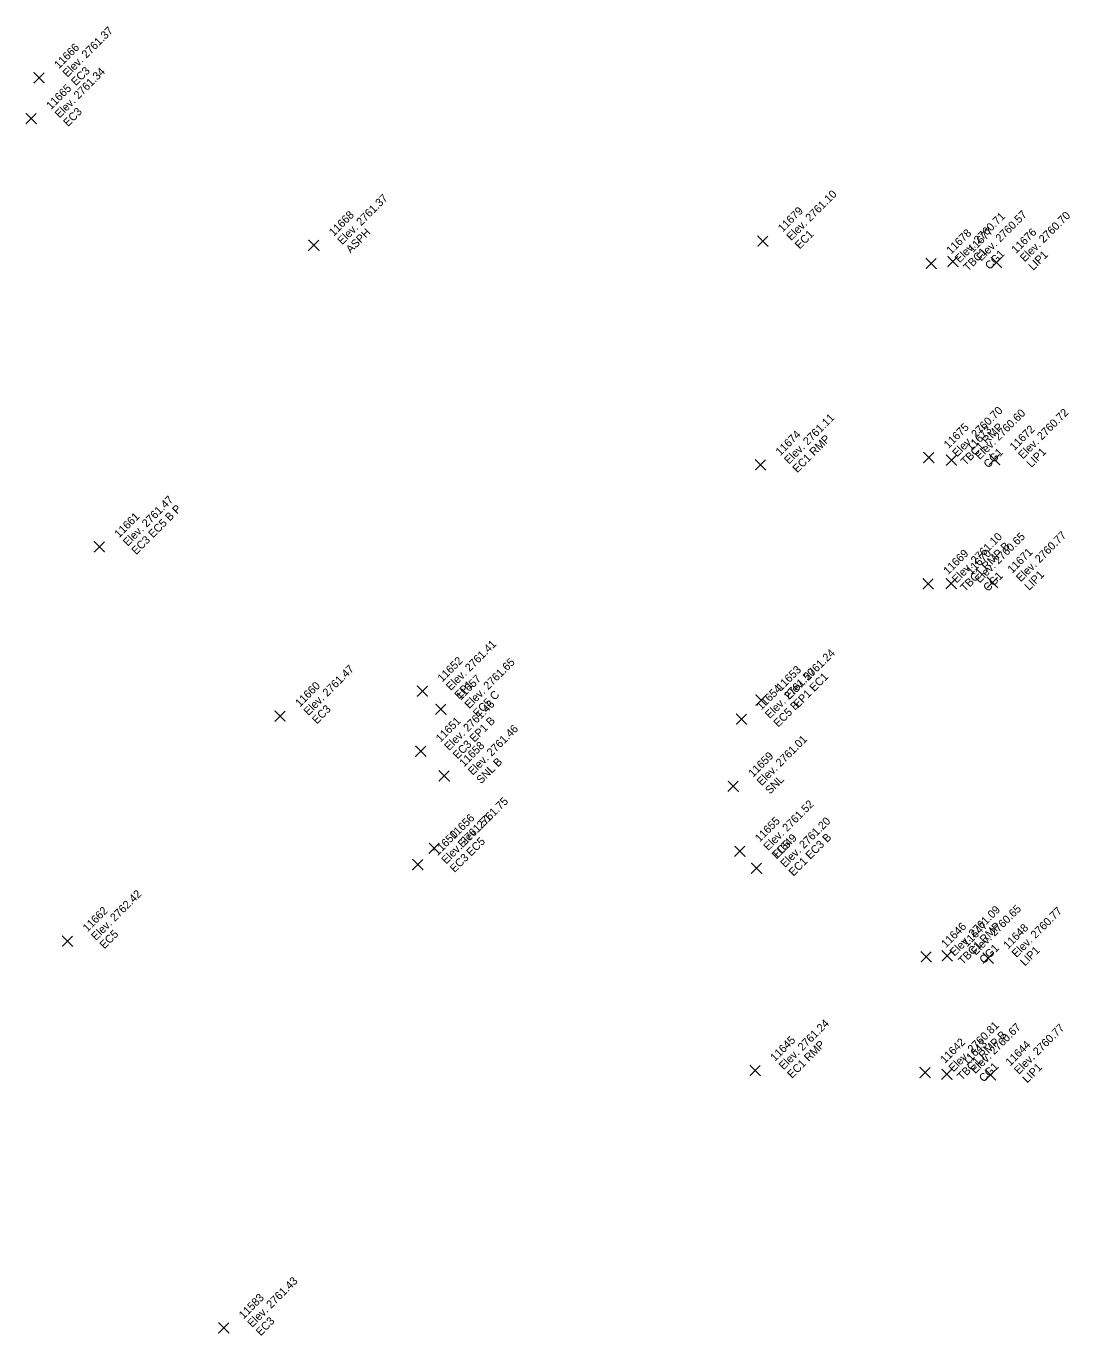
# Model space of a CAD drawing. Extents: x 2493999 to 2503109, y 700767 to 706646.
# Drawn here: x 2502218.73 to 2502250.03, y 701911.21 to 701950.47 of the extents above; entities that cross this region are included whole.
import ezdxf

# ---------------------------------------------------------------- set-up
doc = ezdxf.new("R2010")
doc.units = 0
doc.layers.add('ALG_CL_BLUE_Horiz', color=7, linetype='Continuous')
doc.layers.add('DES_SURFACE_Existing-Ground', color=7, linetype='Continuous')

msp = doc.modelspace()

# ---------------------------------------------------------------- linework, layer by layer
at = {"layer": 'ALG_CL_BLUE_Horiz'}
for points in [[(2502219.122, 701948.922), (2502218.972, 701949.072), (2502219.122, 701948.922), (2502218.972, 701948.772), (2502219.122, 701948.922), (2502219.272, 701948.772), (2502219.122, 701948.922), (2502219.272, 701949.072)], [(2502218.884, 701947.698), (2502218.734, 701947.848), (2502218.884, 701947.698), (2502218.734, 701947.548), (2502218.884, 701947.698), (2502219.034, 701947.548), (2502218.884, 701947.698), (2502219.034, 701947.848)], [(2502240.826, 701944.024), (2502240.676, 701944.174), (2502240.826, 701944.024), (2502240.676, 701943.874), (2502240.826, 701944.024), (2502240.976, 701943.874), (2502240.826, 701944.024), (2502240.976, 701944.174)], [(2502227.36, 701943.902), (2502227.21, 701944.052), (2502227.36, 701943.902), (2502227.21, 701943.752), (2502227.36, 701943.902), (2502227.51, 701943.752), (2502227.36, 701943.902), (2502227.51, 701944.052)], [(2502245.876, 701943.358), (2502245.726, 701943.508), (2502245.876, 701943.358), (2502245.726, 701943.208), (2502245.876, 701943.358), (2502246.026, 701943.208), (2502245.876, 701943.358), (2502246.026, 701943.508)], [(2502246.527, 701943.409), (2502246.377, 701943.559), (2502246.527, 701943.409), (2502246.377, 701943.259), (2502246.527, 701943.409), (2502246.677, 701943.259), (2502246.527, 701943.409), (2502246.677, 701943.559)], [(2502247.828, 701943.383), (2502247.678, 701943.533), (2502247.828, 701943.383), (2502247.678, 701943.233), (2502247.828, 701943.383), (2502247.978, 701943.233), (2502247.828, 701943.383), (2502247.978, 701943.533)], [(2502240.756, 701937.32), (2502240.606, 701937.47), (2502240.756, 701937.32), (2502240.606, 701937.17), (2502240.756, 701937.32), (2502240.906, 701937.17), (2502240.756, 701937.32), (2502240.906, 701937.47)], [(2502245.799, 701937.536), (2502245.649, 701937.686), (2502245.799, 701937.536), (2502245.649, 701937.386), (2502245.799, 701937.536), (2502245.949, 701937.386), (2502245.799, 701937.536), (2502245.949, 701937.686)], [(2502246.482, 701937.458), (2502246.332, 701937.608), (2502246.482, 701937.458), (2502246.332, 701937.308), (2502246.482, 701937.458), (2502246.632, 701937.308), (2502246.482, 701937.458), (2502246.632, 701937.608)], [(2502247.774, 701937.475), (2502247.624, 701937.625), (2502247.774, 701937.475), (2502247.624, 701937.325), (2502247.774, 701937.475), (2502247.924, 701937.325), (2502247.774, 701937.475), (2502247.924, 701937.625)], [(2502220.928, 701934.86), (2502220.778, 701935.01), (2502220.928, 701934.86), (2502220.778, 701934.71), (2502220.928, 701934.86), (2502221.078, 701934.71), (2502220.928, 701934.86), (2502221.078, 701935.01)], [(2502247.709, 701933.794), (2502247.559, 701933.944), (2502247.709, 701933.794), (2502247.559, 701933.644), (2502247.709, 701933.794), (2502247.859, 701933.644), (2502247.709, 701933.794), (2502247.859, 701933.944)], [(2502245.786, 701933.753), (2502245.636, 701933.903), (2502245.786, 701933.753), (2502245.636, 701933.603), (2502245.786, 701933.753), (2502245.936, 701933.603), (2502245.786, 701933.753), (2502245.936, 701933.903)], [(2502246.473, 701933.757), (2502246.323, 701933.907), (2502246.473, 701933.757), (2502246.323, 701933.607), (2502246.473, 701933.757), (2502246.623, 701933.607), (2502246.473, 701933.757), (2502246.623, 701933.907)], [(2502230.618, 701930.534), (2502230.468, 701930.684), (2502230.618, 701930.534), (2502230.468, 701930.384), (2502230.618, 701930.534), (2502230.768, 701930.384), (2502230.618, 701930.534), (2502230.768, 701930.684)], [(2502240.771, 701930.266), (2502240.621, 701930.416), (2502240.771, 701930.266), (2502240.621, 701930.116), (2502240.771, 701930.266), (2502240.921, 701930.116), (2502240.771, 701930.266), (2502240.921, 701930.416)], [(2502231.171, 701929.992), (2502231.021, 701930.142), (2502231.171, 701929.992), (2502231.021, 701929.842), (2502231.171, 701929.992), (2502231.321, 701929.842), (2502231.171, 701929.992), (2502231.321, 701930.142)], [(2502226.346, 701929.787), (2502226.196, 701929.937), (2502226.346, 701929.787), (2502226.196, 701929.637), (2502226.346, 701929.787), (2502226.496, 701929.637), (2502226.346, 701929.787), (2502226.496, 701929.937)], [(2502240.185, 701929.693), (2502240.035, 701929.843), (2502240.185, 701929.693), (2502240.035, 701929.543), (2502240.185, 701929.693), (2502240.335, 701929.543), (2502240.185, 701929.693), (2502240.335, 701929.843)], [(2502230.566, 701928.732), (2502230.416, 701928.882), (2502230.566, 701928.732), (2502230.416, 701928.582), (2502230.566, 701928.732), (2502230.716, 701928.582), (2502230.566, 701928.732), (2502230.716, 701928.882)], [(2502231.272, 701927.994), (2502231.122, 701928.144), (2502231.272, 701927.994), (2502231.122, 701927.844), (2502231.272, 701927.994), (2502231.422, 701927.844), (2502231.272, 701927.994), (2502231.422, 701928.144)], [(2502239.937, 701927.683), (2502239.787, 701927.833), (2502239.937, 701927.683), (2502239.787, 701927.533), (2502239.937, 701927.683), (2502240.087, 701927.533), (2502239.937, 701927.683), (2502240.087, 701927.833)], [(2502230.973, 701925.821), (2502230.823, 701925.971), (2502230.973, 701925.821), (2502230.823, 701925.671), (2502230.973, 701925.821), (2502231.123, 701925.671), (2502230.973, 701925.821), (2502231.123, 701925.971)], [(2502240.135, 701925.735), (2502239.985, 701925.885), (2502240.135, 701925.735), (2502239.985, 701925.585), (2502240.135, 701925.735), (2502240.285, 701925.585), (2502240.135, 701925.735), (2502240.285, 701925.885)], [(2502230.477, 701925.333), (2502230.327, 701925.483), (2502230.477, 701925.333), (2502230.327, 701925.183), (2502230.477, 701925.333), (2502230.627, 701925.183), (2502230.477, 701925.333), (2502230.627, 701925.483)], [(2502240.639, 701925.225), (2502240.489, 701925.375), (2502240.639, 701925.225), (2502240.489, 701925.075), (2502240.639, 701925.225), (2502240.789, 701925.075), (2502240.639, 701925.225), (2502240.789, 701925.375)], [(2502219.976, 701923.042), (2502219.826, 701923.192), (2502219.976, 701923.042), (2502219.826, 701922.892), (2502219.976, 701923.042), (2502220.126, 701922.892), (2502219.976, 701923.042), (2502220.126, 701923.192)], [(2502245.723, 701922.569), (2502245.573, 701922.719), (2502245.723, 701922.569), (2502245.573, 701922.419), (2502245.723, 701922.569), (2502245.873, 701922.419), (2502245.723, 701922.569), (2502245.873, 701922.719)], [(2502246.357, 701922.599), (2502246.207, 701922.749), (2502246.357, 701922.599), (2502246.207, 701922.449), (2502246.357, 701922.599), (2502246.507, 701922.449), (2502246.357, 701922.599), (2502246.507, 701922.749)], [(2502247.583, 701922.529), (2502247.433, 701922.679), (2502247.583, 701922.529), (2502247.433, 701922.379), (2502247.583, 701922.529), (2502247.733, 701922.379), (2502247.583, 701922.529), (2502247.733, 701922.679)], [(2502240.597, 701919.162), (2502240.447, 701919.312), (2502240.597, 701919.162), (2502240.447, 701919.012), (2502240.597, 701919.162), (2502240.747, 701919.012), (2502240.597, 701919.162), (2502240.747, 701919.312)], [(2502245.69, 701919.1), (2502245.54, 701919.25), (2502245.69, 701919.1), (2502245.54, 701918.95), (2502245.69, 701919.1), (2502245.84, 701918.95), (2502245.69, 701919.1), (2502245.84, 701919.25)], [(2502246.346, 701919.049), (2502246.196, 701919.199), (2502246.346, 701919.049), (2502246.196, 701918.899), (2502246.346, 701919.049), (2502246.496, 701918.899), (2502246.346, 701919.049), (2502246.496, 701919.199)], [(2502247.65, 701919.026), (2502247.5, 701919.176), (2502247.65, 701919.026), (2502247.5, 701918.876), (2502247.65, 701919.026), (2502247.8, 701918.876), (2502247.65, 701919.026), (2502247.8, 701919.176)], [(2502224.66, 701911.442), (2502224.51, 701911.592), (2502224.66, 701911.442), (2502224.51, 701911.292), (2502224.66, 701911.442), (2502224.81, 701911.292), (2502224.66, 701911.442), (2502224.81, 701911.592)]]:
    msp.add_lwpolyline(points, dxfattribs=at)

# ---------------------------------------------------------------- texts
at = {"layer": 'DES_SURFACE_Existing-Ground'}
for s, p in [('Elev. 2761.37', (2502219.971, 701948.922)), ('11666', (2502219.716, 701949.177)), ('EC3', (2502220.225, 701948.667)), ('Elev. 2761.34', (2502219.733, 701947.698)), ('11665', (2502219.478, 701947.953)), ('EC3', (2502219.987, 701947.443)), ('Elev. 2761.37', (2502228.209, 701943.902)), ('Elev. 2761.10', (2502241.675, 701944.024)), ('11668', (2502227.954, 701944.157)), ('11679', (2502241.42, 701944.279)), ('Elev. 2760.57', (2502247.376, 701943.409)), ('Elev. 2760.71', (2502246.725, 701943.358)), ('Elev. 2760.70', (2502248.677, 701943.383)), ('ASPH', (2502228.463, 701943.647)), ('EC1', (2502241.929, 701943.769)), ('11678', (2502246.47, 701943.613)), ('11677', (2502247.121, 701943.664)), ('11676', (2502248.422, 701943.638)), ('TBC1', (2502246.979, 701943.103)), ('CG1', (2502247.63, 701943.154)), ('LIP1', (2502248.931, 701943.128)), ('Elev. 2760.70', (2502246.648, 701937.536)), ('Elev. 2761.11', (2502241.605, 701937.32)), ('Elev. 2760.60', (2502247.331, 701937.458)), ('Elev. 2760.72', (2502248.623, 701937.475)), ('11674', (2502241.35, 701937.575)), ('11675', (2502246.393, 701937.791)), ('TBC1 RMP', (2502246.902, 701937.281)), ('11673', (2502247.076, 701937.713)), ('11672', (2502248.368, 701937.73)), ('EC1 RMP', (2502241.859, 701937.065)), ('CG1', (2502247.585, 701937.203)), ('LIP1', (2502248.877, 701937.22)), ('Elev. 2761.47', (2502221.777, 701934.86)), ('EC3 EC5 B P', (2502222.031, 701934.605)), ('11661', (2502221.522, 701935.115)), ('Elev. 2761.10', (2502246.635, 701933.753)), ('Elev. 2760.65', (2502247.322, 701933.757)), ('Elev. 2760.77', (2502248.558, 701933.794)), ('11669', (2502246.38, 701934.008)), ('TBC1 RMP B', (2502246.889, 701933.498)), ('11670', (2502247.067, 701934.012)), ('11671', (2502248.303, 701934.049)), ('CG1', (2502247.576, 701933.502)), ('LIP1', (2502248.812, 701933.539)), ('Elev. 2761.41', (2502231.467, 701930.534)), ('Elev. 2761.24', (2502241.62, 701930.266)), ('Elev. 2761.47', (2502227.195, 701929.787)), ('11652', (2502231.212, 701930.789)), ('Elev. 2761.65', (2502232.02, 701929.992)), ('Elev. 2761.50', (2502241.034, 701929.693)), ('11653', (2502241.365, 701930.521)), ('11660', (2502226.94, 701930.042)), ('EP1', (2502231.721, 701930.279)), ('11657', (2502231.765, 701930.247)), ('EP1 EC1', (2502241.874, 701930.011)), ('EC5 C', (2502232.274, 701929.737)), ('11654', (2502240.779, 701929.948)), ('EC3', (2502227.449, 701929.532)), ('Elev. 2761.46', (2502231.415, 701928.732)), ('EC5 B', (2502241.288, 701929.438)), ('11651', (2502231.16, 701928.987)), ('EC3 EP1 B', (2502231.669, 701928.477)), ('Elev. 2761.46', (2502232.121, 701927.994)), ('11658', (2502231.866, 701928.249)), ('Elev. 2761.01', (2502240.786, 701927.683)), ('SNL B', (2502232.375, 701927.739)), ('11659', (2502240.531, 701927.938)), ('SNL', (2502241.04, 701927.428)), ('Elev. 2761.75', (2502231.822, 701925.821)), ('Elev. 2761.52', (2502240.984, 701925.735)), ('11656', (2502231.567, 701926.076)), ('Elev. 2761.51', (2502231.326, 701925.333)), ('11655', (2502240.729, 701925.99)), ('Elev. 2761.20', (2502241.488, 701925.225)), ('11650', (2502231.071, 701925.588)), ('EC5', (2502232.076, 701925.566)), ('EC5', (2502241.238, 701925.48)), ('11649', (2502241.233, 701925.48)), ('EC1 EC3 B', (2502241.742, 701924.97)), ('EC3', (2502231.58, 701925.078)), ('Elev. 2762.42', (2502220.825, 701923.042)), ('Elev. 2760.65', (2502247.206, 701922.599)), ('11662', (2502220.57, 701923.297)), ('Elev. 2761.09', (2502246.572, 701922.569)), ('Elev. 2760.77', (2502248.432, 701922.529)), ('EC5', (2502221.079, 701922.787)), ('11646', (2502246.317, 701922.824)), ('TBC1 RMP', (2502246.826, 701922.314)), ('11647', (2502246.951, 701922.854)), ('11648', (2502248.177, 701922.784)), ('CG1', (2502247.46, 701922.344)), ('LIP1', (2502248.686, 701922.274)), ('Elev. 2761.24', (2502241.446, 701919.162)), ('Elev. 2760.81', (2502246.539, 701919.1)), ('Elev. 2760.67', (2502247.195, 701919.049)), ('Elev. 2760.77', (2502248.499, 701919.026)), ('11645', (2502241.191, 701919.417)), ('TBC1 RMP B', (2502246.793, 701918.845)), ('EC1 RMP', (2502241.7, 701918.907)), ('11642', (2502246.284, 701919.355)), ('11643', (2502246.94, 701919.304)), ('11644', (2502248.244, 701919.281)), ('CG1', (2502247.449, 701918.794)), ('LIP1', (2502248.753, 701918.771)), ('Elev. 2761.43', (2502225.509, 701911.442)), ('11583', (2502225.254, 701911.697)), ('EC3', (2502225.763, 701911.187))]:
    msp.add_text(s, height=0.24, rotation=45, dxfattribs=at).set_placement(p)

doc.saveas('drawing.dxf')
